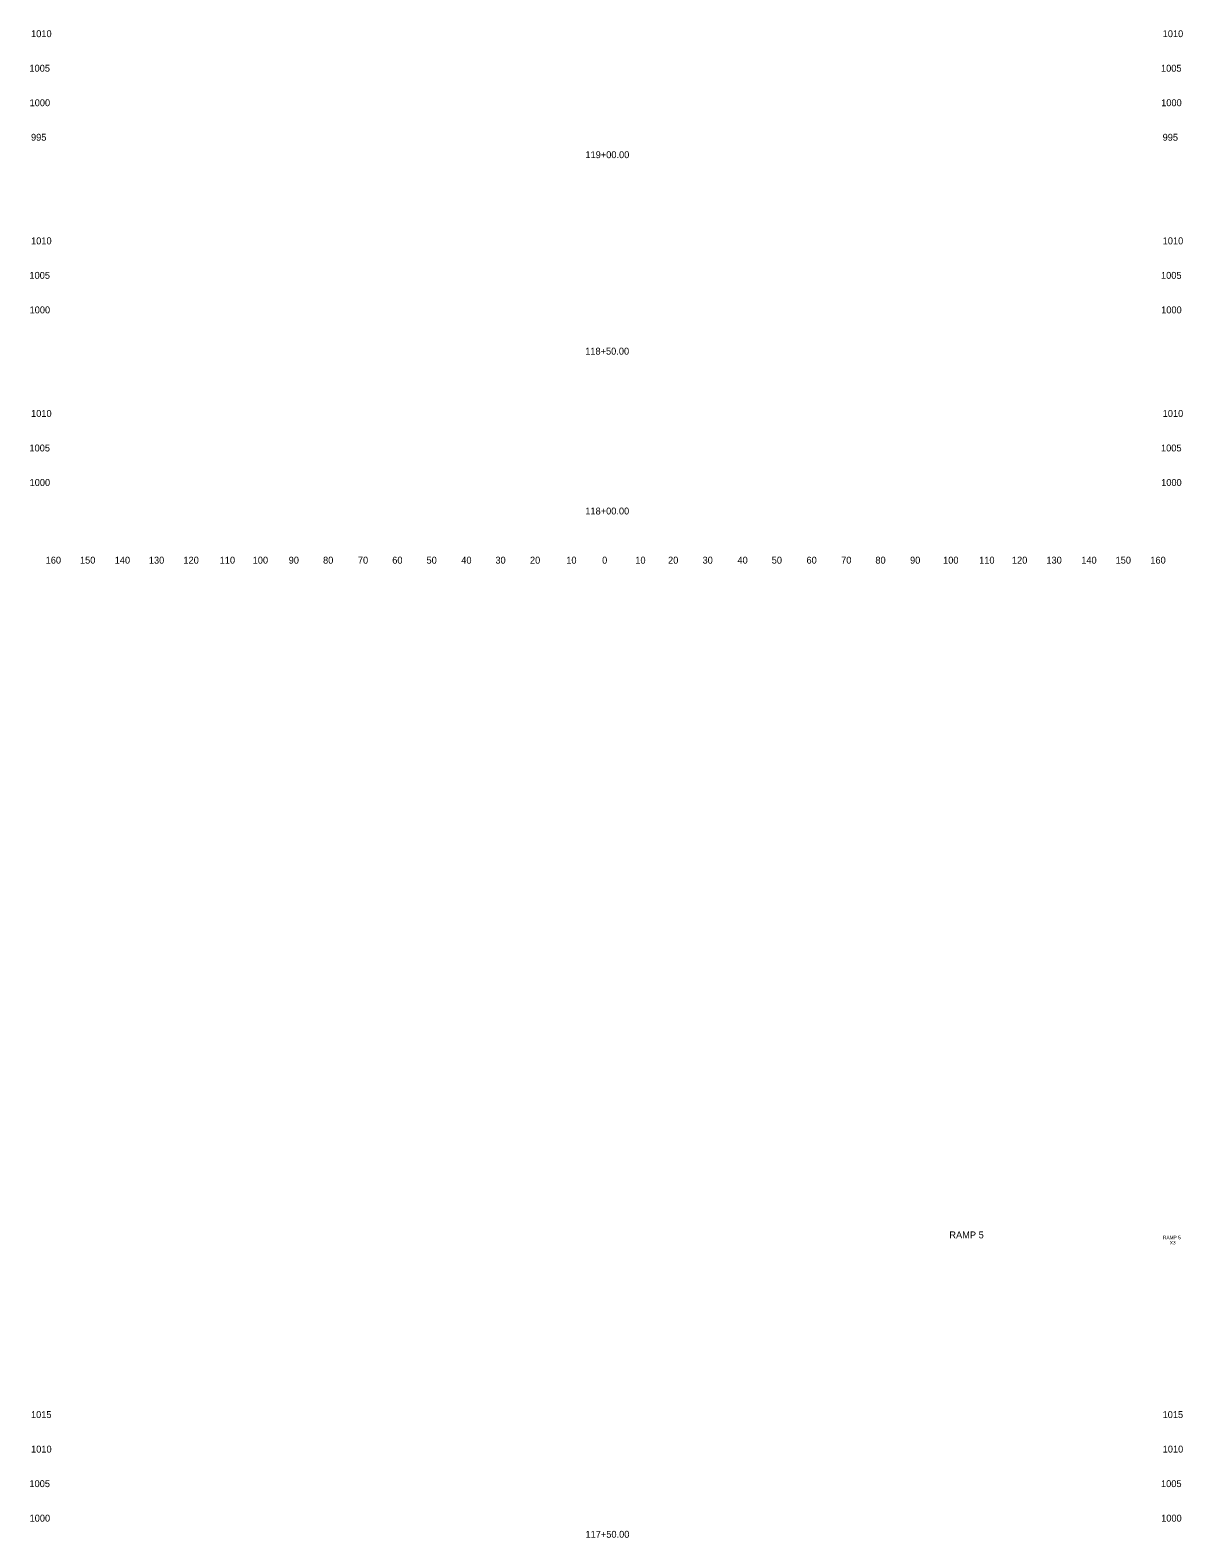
# Model space of a CAD drawing. Extents: x 4994 to 5842, y 4997 to 8804.
# Drawn here: x 4993.6 to 5327.5, y 5915.3 to 6352 of the extents above; entities that cross this region are included whole.
import ezdxf

# ---------------------------------------------------------------- set-up
doc = ezdxf.new("R2010")
doc.units = 0
for name, color, linetype in [('CLS_Search_Dist', 7, 'Continuous'), ('RD_XE_Ground', 7, 'Continuous'), ('UC_PD_Text', 7, 'Continuous')]:
    doc.layers.add(name, color=color, linetype=linetype)

msp = doc.modelspace()

# ---------------------------------------------------------------- texts
at = {"layer": 'CLS_Search_Dist'}
for s, p in [('1010', (4993.88, 6350)), ('1010', (5321.68, 6350)), ('1005', (4993.4, 6340)), ('1005', (5321.2, 6340)), ('1000', (4993.44, 6330)), ('1000', (5321.24, 6330)), ('995', (4993.86, 6320)), ('995', (5321.66, 6320)), ('1010', (4993.88, 6290)), ('1010', (5321.68, 6290)), ('1005', (4993.4, 6280)), ('1005', (5321.2, 6280)), ('1000', (4993.44, 6270)), ('1000', (5321.24, 6270)), ('1010', (4993.88, 6240)), ('1010', (5321.68, 6240)), ('1005', (4993.4, 6230)), ('1005', (5321.2, 6230)), ('1000', (4993.44, 6220)), ('1000', (5321.24, 6220)), ('160', (4998.1, 6197.5)), ('150', (5008.04, 6197.5)), ('140', (5018.1, 6197.5)), ('130', (5027.99, 6197.5)), ('120', (5038.01, 6197.5)), ('110', (5048.51, 6197.5)), ('100', (5058.07, 6197.5)), ('90', (5068.5, 6197.5)), ('80', (5078.46, 6197.5)), ('70', (5088.54, 6197.5)), ('60', (5098.5, 6197.5)), ('50', (5108.43, 6197.5)), ('40', (5118.5, 6197.5)), ('30', (5128.39, 6197.5)), ('20', (5138.4, 6197.5)), ('10', (5148.91, 6197.5)), ('0', (5159.3, 6197.5)), ('0', (5159.3, 6197.5)), ('10', (5168.91, 6197.5)), ('20', (5178.4, 6197.5)), ('30', (5188.39, 6197.5)), ('40', (5198.5, 6197.5)), ('50', (5208.43, 6197.5)), ('60', (5218.5, 6197.5)), ('70', (5228.54, 6197.5)), ('80', (5238.46, 6197.5)), ('90', (5248.5, 6197.5)), ('100', (5258.07, 6197.5)), ('110', (5268.51, 6197.5)), ('120', (5278.01, 6197.5)), ('130', (5287.99, 6197.5)), ('140', (5298.1, 6197.5)), ('150', (5308.04, 6197.5)), ('160', (5318.1, 6197.5)), ('1015', (4993.85, 5950)), ('1015', (5321.65, 5950)), ('1010', (4993.88, 5940)), ('1010', (5321.68, 5940)), ('1005', (4993.4, 5930)), ('1005', (5321.2, 5930)), ('1000', (4993.44, 5920)), ('1000', (5321.24, 5920))]:
    msp.add_text(s, height=2, dxfattribs=at).set_placement(p)
at = {"layer": 'RD_XE_Ground'}
for s, p in [('119+00.00', (5154.46, 6314.95)), ('118+50.00', (5154.4, 6258.04)), ('118+00.00', (5154.43, 6211.74)), ('117+50.00', (5154.48, 5915.33))]:
    msp.add_text(s, height=2, dxfattribs=at).set_placement(p)
at = {"layer": 'UC_PD_Text'}
for s, height, p in [('RAMP 5', 2, (5259.89, 6002.06)), ('RAMP 5', 1, (5321.78, 6001.8)), ('X3', 1, (5323.74, 6000.3))]:
    msp.add_text(s, height=height, dxfattribs=at).set_placement(p)

doc.saveas('drawing.dxf')
